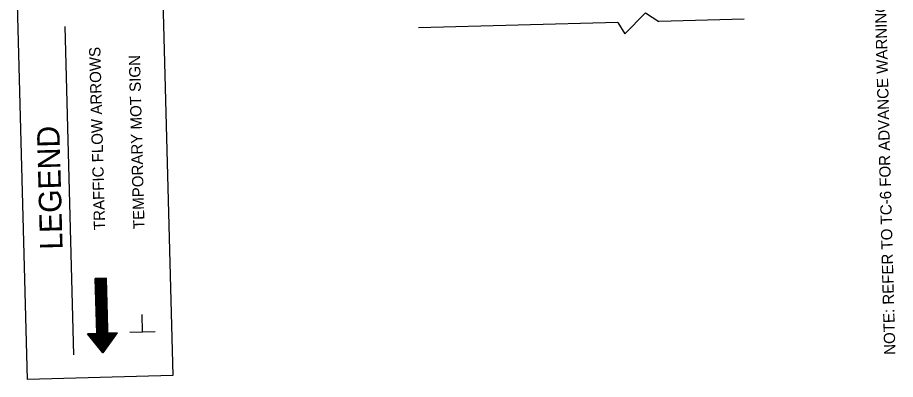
# Model space of a CAD drawing. Extents: x 1929653 to 1931621, y 596452 to 600944.
# Drawn here: x 1930655.2 to 1931122.8, y 597026.7 to 597219.5 of the extents above; entities that cross this region are included whole.
import ezdxf

# ---------------------------------------------------------------- set-up
doc = ezdxf.new("R2010")
doc.units = 0
doc.layers.add('R_Border', color=7, linetype='Continuous')
doc.layers.add('R_Draft', color=7, linetype='Continuous')

msp = doc.modelspace()

# ---------------------------------------------------------------- linework, layer by layer
at = {"layer": 'R_Border'}
for p, q in [((1930685.23, 597039.86), (1930680.53, 597214.8)), ((1930696.58, 597080.53), (1930702.73, 597074.7)), ((1930696.59, 597080.39), (1930702.73, 597074.56)), ((1930696.59, 597080.24), (1930702.73, 597074.42)), ((1930696.59, 597080.1), (1930702.74, 597074.28)), ((1930696.6, 597079.96), (1930702.74, 597074.14)), ((1930696.6, 597079.82), (1930702.74, 597074)), ((1930696.61, 597079.68), (1930702.75, 597073.86)), ((1930696.61, 597079.54), (1930702.75, 597073.71)), ((1930696.61, 597079.4), (1930702.76, 597073.57)), ((1930696.62, 597079.25), (1930702.76, 597073.43)), ((1930696.62, 597079.11), (1930702.76, 597073.29)), ((1930696.62, 597078.97), (1930702.77, 597073.15)), ((1930696.63, 597078.83), (1930702.77, 597073.01)), ((1930696.63, 597078.69), (1930702.77, 597072.87)), ((1930696.64, 597078.55), (1930702.78, 597072.73)), ((1930696.64, 597078.41), (1930702.78, 597072.58)), ((1930696.64, 597078.26), (1930702.79, 597072.44)), ((1930696.65, 597078.12), (1930702.79, 597072.3)), ((1930696.65, 597077.98), (1930702.79, 597072.16)), ((1930696.71, 597080.55), (1930702.72, 597074.85)), ((1930696.85, 597080.55), (1930702.72, 597074.99)), ((1930696.99, 597080.55), (1930702.71, 597075.13)), ((1930697.13, 597080.56), (1930702.71, 597075.27)), ((1930697.27, 597080.56), (1930702.71, 597075.41)), ((1930697.41, 597080.57), (1930702.7, 597075.55)), ((1930697.55, 597080.57), (1930702.7, 597075.69)), ((1930697.7, 597080.57), (1930702.69, 597075.84)), ((1930697.84, 597080.58), (1930702.69, 597075.98)), ((1930697.98, 597080.58), (1930702.69, 597076.12)), ((1930698.12, 597080.58), (1930702.68, 597076.26)), ((1930698.26, 597080.59), (1930702.68, 597076.4)), ((1930698.4, 597080.59), (1930702.68, 597076.54)), ((1930698.54, 597080.6), (1930702.67, 597076.68)), ((1930698.69, 597080.6), (1930702.67, 597076.83)), ((1930698.83, 597080.6), (1930702.66, 597076.97)), ((1930698.97, 597080.61), (1930702.66, 597077.11)), ((1930699.11, 597080.61), (1930702.66, 597077.25)), ((1930699.25, 597080.61), (1930702.65, 597077.39)), ((1930699.39, 597080.62), (1930702.65, 597077.53)), ((1930699.53, 597080.62), (1930702.65, 597077.67)), ((1930699.68, 597080.63), (1930702.64, 597077.81)), ((1930699.82, 597080.63), (1930702.64, 597077.96)), ((1930699.96, 597080.63), (1930702.63, 597078.1)), ((1930700.1, 597080.64), (1930702.63, 597078.24)), ((1930700.24, 597080.64), (1930702.63, 597078.38)), ((1930700.38, 597080.65), (1930702.62, 597078.52)), ((1930700.52, 597080.65), (1930702.62, 597078.66)), ((1930700.66, 597080.65), (1930702.62, 597078.8)), ((1930700.81, 597080.66), (1930702.61, 597078.95)), ((1930700.95, 597080.66), (1930702.61, 597079.09)), ((1930701.09, 597080.66), (1930702.6, 597079.23)), ((1930701.23, 597080.67), (1930702.6, 597079.37)), ((1930701.37, 597080.67), (1930702.6, 597079.51)), ((1930701.51, 597080.68), (1930702.59, 597079.65)), ((1930701.65, 597080.68), (1930702.59, 597079.79)), ((1930701.8, 597080.68), (1930702.58, 597079.94)), ((1930701.94, 597080.69), (1930702.58, 597080.08)), ((1930702.08, 597080.69), (1930702.58, 597080.22)), ((1930702.22, 597080.69), (1930702.57, 597080.36)), ((1930702.36, 597080.7), (1930702.57, 597080.5)), ((1930702.5, 597080.7), (1930702.57, 597080.64)), ((1930696.65, 597077.84), (1930702.8, 597072.02)), ((1930696.66, 597077.7), (1930702.8, 597071.88)), ((1930696.66, 597077.56), (1930702.81, 597071.74)), ((1930696.67, 597077.42), (1930702.81, 597071.59)), ((1930696.67, 597077.27), (1930702.81, 597071.45)), ((1930696.67, 597077.13), (1930702.82, 597071.31)), ((1930696.68, 597076.99), (1930702.82, 597071.17)), ((1930696.68, 597076.85), (1930702.82, 597071.03)), ((1930696.68, 597076.71), (1930702.83, 597070.89)), ((1930696.69, 597076.57), (1930702.83, 597070.75)), ((1930696.69, 597076.43), (1930702.84, 597070.6)), ((1930696.7, 597076.29), (1930702.84, 597070.46)), ((1930696.7, 597076.14), (1930702.84, 597070.32)), ((1930696.7, 597076), (1930702.85, 597070.18)), ((1930696.71, 597075.86), (1930702.85, 597070.04)), ((1930696.71, 597075.72), (1930702.85, 597069.9)), ((1930696.72, 597075.58), (1930702.86, 597069.76)), ((1930696.72, 597075.44), (1930702.86, 597069.62)), ((1930696.72, 597075.3), (1930702.87, 597069.47)), ((1930696.73, 597075.15), (1930702.87, 597069.33)), ((1930696.73, 597075.01), (1930702.87, 597069.19)), ((1930696.73, 597074.87), (1930702.88, 597069.05)), ((1930696.74, 597074.73), (1930702.88, 597068.91)), ((1930696.74, 597074.59), (1930702.88, 597068.77)), ((1930696.75, 597074.45), (1930702.89, 597068.63)), ((1930696.75, 597074.31), (1930702.89, 597068.48)), ((1930696.75, 597074.16), (1930702.9, 597068.34)), ((1930696.76, 597074.02), (1930702.9, 597068.2)), ((1930696.76, 597073.88), (1930702.9, 597068.06)), ((1930696.76, 597073.74), (1930702.91, 597067.92)), ((1930696.77, 597073.6), (1930702.91, 597067.78)), ((1930696.77, 597073.46), (1930702.92, 597067.64)), ((1930696.78, 597073.32), (1930702.92, 597067.49)), ((1930696.78, 597073.18), (1930702.92, 597067.35)), ((1930696.78, 597073.03), (1930702.93, 597067.21)), ((1930696.79, 597072.89), (1930702.93, 597067.07)), ((1930696.79, 597072.75), (1930702.93, 597066.93)), ((1930696.79, 597072.61), (1930702.94, 597066.79)), ((1930696.8, 597072.47), (1930702.94, 597066.65)), ((1930696.8, 597072.33), (1930702.95, 597066.51)), ((1930696.81, 597072.19), (1930702.95, 597066.36)), ((1930696.81, 597072.04), (1930702.95, 597066.22)), ((1930696.81, 597071.9), (1930702.96, 597066.08)), ((1930696.82, 597071.76), (1930702.96, 597065.94)), ((1930696.82, 597071.62), (1930702.96, 597065.8)), ((1930696.83, 597071.48), (1930702.97, 597065.66)), ((1930696.83, 597071.34), (1930702.97, 597065.52)), ((1930696.83, 597071.2), (1930702.98, 597065.37)), ((1930696.84, 597071.05), (1930702.98, 597065.23)), ((1930696.84, 597070.91), (1930702.98, 597065.09)), ((1930696.84, 597070.77), (1930702.99, 597064.95)), ((1930696.85, 597070.63), (1930702.99, 597064.81)), ((1930696.85, 597070.49), (1930702.99, 597064.67)), ((1930696.86, 597070.35), (1930703, 597064.53)), ((1930696.86, 597070.21), (1930703, 597064.38)), ((1930696.86, 597070.06), (1930703.01, 597064.24)), ((1930696.87, 597069.92), (1930703.01, 597064.1)), ((1930696.87, 597069.78), (1930703.01, 597063.96)), ((1930696.87, 597069.64), (1930703.02, 597063.82)), ((1930696.88, 597069.5), (1930703.02, 597063.68)), ((1930696.88, 597069.36), (1930703.03, 597063.54)), ((1930696.89, 597069.22), (1930703.03, 597063.39)), ((1930696.89, 597069.08), (1930703.03, 597063.25)), ((1930696.89, 597068.93), (1930703.04, 597063.11)), ((1930696.9, 597068.79), (1930703.04, 597062.97)), ((1930696.9, 597068.65), (1930703.04, 597062.83)), ((1930696.9, 597068.51), (1930703.05, 597062.69)), ((1930696.91, 597068.37), (1930703.05, 597062.55)), ((1930696.91, 597068.23), (1930703.06, 597062.41)), ((1930696.92, 597068.09), (1930703.06, 597062.26)), ((1930696.92, 597067.94), (1930703.06, 597062.12)), ((1930696.92, 597067.8), (1930703.07, 597061.98)), ((1930696.93, 597067.66), (1930703.07, 597061.84)), ((1930696.93, 597067.52), (1930703.07, 597061.7)), ((1930696.94, 597067.38), (1930703.08, 597061.56)), ((1930696.94, 597067.24), (1930703.08, 597061.42)), ((1930696.94, 597067.1), (1930703.09, 597061.27)), ((1930696.95, 597066.95), (1930703.09, 597061.13)), ((1930696.95, 597066.81), (1930703.09, 597060.99)), ((1930696.95, 597066.67), (1930703.1, 597060.85)), ((1930696.96, 597066.53), (1930703.1, 597060.71)), ((1930696.96, 597066.39), (1930703.1, 597060.57)), ((1930696.97, 597066.25), (1930703.11, 597060.43)), ((1930696.97, 597066.11), (1930703.11, 597060.28)), ((1930696.97, 597065.97), (1930703.12, 597060.14)), ((1930696.98, 597065.82), (1930703.12, 597060)), ((1930696.98, 597065.68), (1930703.12, 597059.86)), ((1930696.98, 597065.54), (1930703.13, 597059.72)), ((1930696.99, 597065.4), (1930703.13, 597059.58)), ((1930696.99, 597065.26), (1930703.14, 597059.44)), ((1930697, 597065.12), (1930703.14, 597059.3)), ((1930697, 597064.98), (1930703.14, 597059.15)), ((1930697, 597064.83), (1930703.15, 597059.01)), ((1930697.01, 597064.69), (1930703.15, 597058.87)), ((1930697.01, 597064.55), (1930703.15, 597058.73)), ((1930697.01, 597064.41), (1930703.16, 597058.59)), ((1930697.02, 597064.27), (1930703.16, 597058.45)), ((1930697.02, 597064.13), (1930703.17, 597058.31)), ((1930697.03, 597063.99), (1930703.17, 597058.16)), ((1930697.03, 597063.84), (1930703.17, 597058.02)), ((1930697.03, 597063.7), (1930703.18, 597057.88)), ((1930697.04, 597063.56), (1930703.18, 597057.74)), ((1930697.04, 597063.42), (1930703.18, 597057.6)), ((1930697.05, 597063.28), (1930703.19, 597057.46)), ((1930697.05, 597063.14), (1930703.19, 597057.32)), ((1930697.05, 597063), (1930703.2, 597057.17)), ((1930697.06, 597062.86), (1930703.2, 597057.03)), ((1930697.06, 597062.71), (1930703.2, 597056.89)), ((1930697.06, 597062.57), (1930703.21, 597056.75)), ((1930697.07, 597062.43), (1930703.21, 597056.61)), ((1930697.07, 597062.29), (1930703.21, 597056.47)), ((1930697.08, 597062.15), (1930703.22, 597056.33)), ((1930697.08, 597062.01), (1930703.22, 597056.18)), ((1930697.08, 597061.87), (1930703.23, 597056.04)), ((1930697.09, 597061.72), (1930703.23, 597055.9)), ((1930697.09, 597061.58), (1930703.23, 597055.76)), ((1930697.09, 597061.44), (1930703.24, 597055.62)), ((1930697.1, 597061.3), (1930703.24, 597055.48)), ((1930697.1, 597061.16), (1930703.25, 597055.34)), ((1930697.11, 597061.02), (1930703.25, 597055.2)), ((1930697.11, 597060.88), (1930703.25, 597055.05)), ((1930697.11, 597060.73), (1930703.26, 597054.91)), ((1930697.12, 597060.59), (1930703.26, 597054.77)), ((1930697.12, 597060.45), (1930703.26, 597054.63)), ((1930697.12, 597060.31), (1930703.27, 597054.49)), ((1930697.13, 597060.17), (1930703.27, 597054.35)), ((1930697.13, 597060.03), (1930703.28, 597054.21)), ((1930697.14, 597059.89), (1930703.28, 597054.06)), ((1930697.14, 597059.74), (1930703.28, 597053.92)), ((1930697.14, 597059.6), (1930703.29, 597053.78)), ((1930697.15, 597059.46), (1930703.29, 597053.64)), ((1930697.15, 597059.32), (1930703.29, 597053.5)), ((1930697.16, 597059.18), (1930703.3, 597053.36)), ((1930697.16, 597059.04), (1930703.3, 597053.22)), ((1930697.16, 597058.9), (1930703.31, 597053.07)), ((1930697.17, 597058.76), (1930703.31, 597052.93)), ((1930697.17, 597058.61), (1930703.31, 597052.79)), ((1930697.17, 597058.47), (1930703.32, 597052.65)), ((1930697.18, 597058.33), (1930703.32, 597052.51)), ((1930697.18, 597058.19), (1930703.32, 597052.37)), ((1930697.19, 597058.05), (1930703.33, 597052.23)), ((1930697.19, 597057.91), (1930703.33, 597052.09)), ((1930697.19, 597057.77), (1930703.34, 597051.94)), ((1930697.2, 597057.62), (1930703.34, 597051.8)), ((1930697.2, 597057.48), (1930703.34, 597051.66)), ((1930697.2, 597057.34), (1930703.35, 597051.52)), ((1930697.21, 597057.2), (1930703.35, 597051.38)), ((1930697.21, 597057.06), (1930706.19, 597048.55)), ((1930697.22, 597056.92), (1930706.13, 597048.47)), ((1930697.22, 597056.78), (1930706.07, 597048.39)), ((1930697.22, 597056.63), (1930706.01, 597048.31)), ((1930697.23, 597056.49), (1930705.95, 597048.23)), ((1930697.23, 597056.35), (1930705.89, 597048.14)), ((1930697.23, 597056.21), (1930705.83, 597048.06)), ((1930697.24, 597056.07), (1930705.77, 597047.98)), ((1930697.24, 597055.93), (1930705.71, 597047.9)), ((1930697.25, 597055.79), (1930705.65, 597047.82)), ((1930697.25, 597055.65), (1930705.59, 597047.74)), ((1930697.25, 597055.5), (1930705.54, 597047.66)), ((1930697.26, 597055.36), (1930705.48, 597047.57)), ((1930697.26, 597055.22), (1930705.42, 597047.49)), ((1930697.27, 597055.08), (1930705.36, 597047.41)), ((1930697.27, 597054.94), (1930705.3, 597047.33)), ((1930697.27, 597054.8), (1930705.24, 597047.25)), ((1930697.28, 597054.66), (1930705.18, 597047.17)), ((1930692.48, 597051.07), (1930701.68, 597042.36)), ((1930692.55, 597050.87), (1930701.62, 597042.28)), ((1930692.62, 597051.08), (1930701.73, 597042.44)), ((1930692.76, 597051.08), (1930701.79, 597042.52)), ((1930692.9, 597051.09), (1930701.85, 597042.6)), ((1930693.04, 597051.09), (1930701.91, 597042.68)), ((1930693.04, 597050.27), (1930701.56, 597042.2)), ((1930693.18, 597051.09), (1930701.97, 597042.77)), ((1930693.33, 597051.1), (1930702.03, 597042.85)), ((1930693.47, 597051.1), (1930702.09, 597042.93)), ((1930693.61, 597051.11), (1930702.15, 597043.01)), ((1930693.75, 597051.11), (1930702.21, 597043.09)), ((1930693.89, 597051.11), (1930702.27, 597043.17)), ((1930694.03, 597051.12), (1930702.33, 597043.25)), ((1930694.17, 597051.12), (1930702.39, 597043.34)), ((1930694.32, 597051.12), (1930702.45, 597043.42)), ((1930694.46, 597051.13), (1930702.51, 597043.5)), ((1930694.6, 597051.13), (1930702.57, 597043.58)), ((1930694.74, 597051.14), (1930702.63, 597043.66)), ((1930694.88, 597051.14), (1930702.68, 597043.74)), ((1930695.02, 597051.14), (1930702.74, 597043.83)), ((1930695.16, 597051.15), (1930702.8, 597043.91)), ((1930695.31, 597051.15), (1930702.86, 597043.99)), ((1930695.45, 597051.15), (1930702.92, 597044.07)), ((1930695.59, 597051.16), (1930702.98, 597044.15)), ((1930695.73, 597051.16), (1930703.04, 597044.23)), ((1930695.87, 597051.17), (1930703.1, 597044.31)), ((1930696.01, 597051.17), (1930703.16, 597044.4)), ((1930696.15, 597051.17), (1930703.22, 597044.48)), ((1930696.29, 597051.18), (1930703.28, 597044.56)), ((1930696.44, 597051.18), (1930703.34, 597044.64)), ((1930696.58, 597051.18), (1930703.4, 597044.72)), ((1930696.72, 597051.19), (1930703.46, 597044.8)), ((1930696.86, 597051.19), (1930703.52, 597044.88)), ((1930697, 597051.2), (1930703.58, 597044.97)), ((1930697.14, 597051.2), (1930703.64, 597045.05)), ((1930697.28, 597054.51), (1930705.12, 597047.08)), ((1930697.28, 597054.37), (1930705.06, 597047)), ((1930697.28, 597051.2), (1930703.69, 597045.13)), ((1930697.29, 597054.23), (1930705, 597046.92)), ((1930697.29, 597054.09), (1930704.94, 597046.84)), ((1930697.3, 597053.95), (1930704.88, 597046.76)), ((1930697.3, 597053.81), (1930704.82, 597046.68)), ((1930697.3, 597053.67), (1930704.76, 597046.6)), ((1930697.31, 597053.52), (1930704.7, 597046.51)), ((1930697.31, 597053.38), (1930704.64, 597046.43)), ((1930697.31, 597053.24), (1930704.59, 597046.35)), ((1930697.32, 597053.1), (1930704.53, 597046.27)), ((1930697.32, 597052.96), (1930704.47, 597046.19)), ((1930697.33, 597052.82), (1930704.41, 597046.11)), ((1930697.33, 597052.68), (1930704.35, 597046.03)), ((1930697.33, 597052.54), (1930704.29, 597045.94)), ((1930697.34, 597052.39), (1930704.23, 597045.86)), ((1930697.34, 597052.25), (1930704.17, 597045.78)), ((1930697.35, 597052.11), (1930704.11, 597045.7)), ((1930697.35, 597051.97), (1930704.05, 597045.62)), ((1930697.35, 597051.83), (1930703.99, 597045.54)), ((1930697.36, 597051.69), (1930703.93, 597045.46)), ((1930697.36, 597051.55), (1930703.87, 597045.37)), ((1930697.36, 597051.4), (1930703.81, 597045.29)), ((1930697.37, 597051.26), (1930703.75, 597045.21)), ((1930703.36, 597051.37), (1930706.25, 597048.63)), ((1930703.5, 597051.37), (1930706.31, 597048.71)), ((1930703.65, 597051.37), (1930706.37, 597048.8)), ((1930703.79, 597051.38), (1930706.43, 597048.88)), ((1930703.93, 597051.38), (1930706.49, 597048.96)), ((1930704.07, 597051.39), (1930706.54, 597049.04)), ((1930704.21, 597051.39), (1930706.6, 597049.12)), ((1930704.35, 597051.39), (1930706.66, 597049.2)), ((1930704.49, 597051.4), (1930706.72, 597049.29)), ((1930704.64, 597051.4), (1930706.78, 597049.37)), ((1930704.78, 597051.41), (1930706.84, 597049.45)), ((1930704.92, 597051.41), (1930706.9, 597049.53)), ((1930705.06, 597051.41), (1930706.96, 597049.61)), ((1930705.2, 597051.42), (1930707.02, 597049.69)), ((1930705.34, 597051.42), (1930707.08, 597049.77)), ((1930705.48, 597051.42), (1930707.14, 597049.86)), ((1930705.63, 597051.43), (1930707.2, 597049.94)), ((1930705.77, 597051.43), (1930707.26, 597050.02)), ((1930705.91, 597051.44), (1930707.32, 597050.1)), ((1930706.05, 597051.44), (1930707.38, 597050.18)), ((1930706.19, 597051.44), (1930707.44, 597050.26)), ((1930706.33, 597051.45), (1930707.49, 597050.34)), ((1930706.47, 597051.45), (1930707.55, 597050.43)), ((1930706.61, 597051.45), (1930707.61, 597050.51)), ((1930706.76, 597051.46), (1930707.67, 597050.59)), ((1930706.9, 597051.46), (1930707.73, 597050.67)), ((1930707.04, 597051.47), (1930707.79, 597050.75)), ((1930707.18, 597051.47), (1930707.85, 597050.83)), ((1930707.32, 597051.47), (1930707.91, 597050.92)), ((1930707.46, 597051.48), (1930707.97, 597051)), ((1930707.6, 597051.48), (1930708.03, 597051.08)), ((1930707.75, 597051.48), (1930708.09, 597051.16)), ((1930707.89, 597051.49), (1930708.15, 597051.24)), ((1930708.03, 597051.49), (1930708.21, 597051.32)), ((1930708.17, 597051.5), (1930708.27, 597051.4)), ((1930708.31, 597051.5), (1930708.33, 597051.49)), ((1930693.53, 597049.66), (1930701.5, 597042.11)), ((1930694.02, 597049.06), (1930701.44, 597042.03)), ((1930694.51, 597048.46), (1930701.38, 597041.95)), ((1930695.01, 597047.85), (1930701.32, 597041.87)), ((1930695.5, 597047.25), (1930701.26, 597041.79)), ((1930695.99, 597046.65), (1930701.2, 597041.71)), ((1930696.48, 597046.04), (1930701.14, 597041.62)), ((1930696.97, 597045.44), (1930701.08, 597041.54)), ((1930697.46, 597044.84), (1930701.02, 597041.46)), ((1930697.95, 597044.23), (1930700.96, 597041.38)), ((1930698.45, 597043.63), (1930700.9, 597041.3)), ((1930698.94, 597043.02), (1930700.84, 597041.22)), ((1930699.43, 597042.42), (1930700.78, 597041.14)), ((1930699.92, 597041.82), (1930700.73, 597041.05)), ((1930700.41, 597041.21), (1930700.67, 597040.97))]:
    msp.add_line(p, q, dxfattribs=at)
msp.add_lwpolyline([(1930660.57, 597026.7), (1930655.21, 597226.62), (1930732.63, 597228.7), (1930738, 597028.77)], close=True, dxfattribs=at)
at = {"layer": 'R_Draft'}
for p, q in [((1931042.17, 597218.62), (1930996.71, 597217.4)), ((1930974.9, 597216.82), (1930868.72, 597213.97)), ((1930702.56, 597080.7), (1930696.58, 597080.54)), ((1930697.37, 597051.21), (1930696.58, 597080.54)), ((1930703.35, 597051.37), (1930702.56, 597080.7)), ((1930721.75, 597052.06), (1930721.51, 597061.24)), ((1930697.37, 597051.21), (1930692.38, 597051.07)), ((1930700.64, 597040.94), (1930692.38, 597051.07)), ((1930708.34, 597051.5), (1930700.64, 597040.94)), ((1930708.34, 597051.5), (1930703.35, 597051.37)), ((1930728.46, 597052.04), (1930715, 597051.68))]:
    msp.add_line(p, q, dxfattribs=at)
msp.add_lwpolyline([(1930974.9, 597216.82), (1930978.72, 597210.78), (1930989.72, 597222.03), (1930996.71, 597217.4)], dxfattribs=at)

# ---------------------------------------------------------------- texts
at = {"layer": 'R_Border'}
for s, height, p in [('NOTE: REFER TO TC-6 FOR ADVANCE WARNING DETAILS', 6, (1931122.82, 597039.87)), ('TRAFFIC FLOW ARROWS', 6, (1930701.89, 597106.35)), ('TEMPORARY MOT SIGN', 6, (1930722.88, 597106.91)), ('LEGEND', 12, (1930679.22, 597095.99))]:
    msp.add_text(s, height=height, rotation=91.5377, dxfattribs=at).set_placement(p)

doc.saveas('drawing.dxf')
